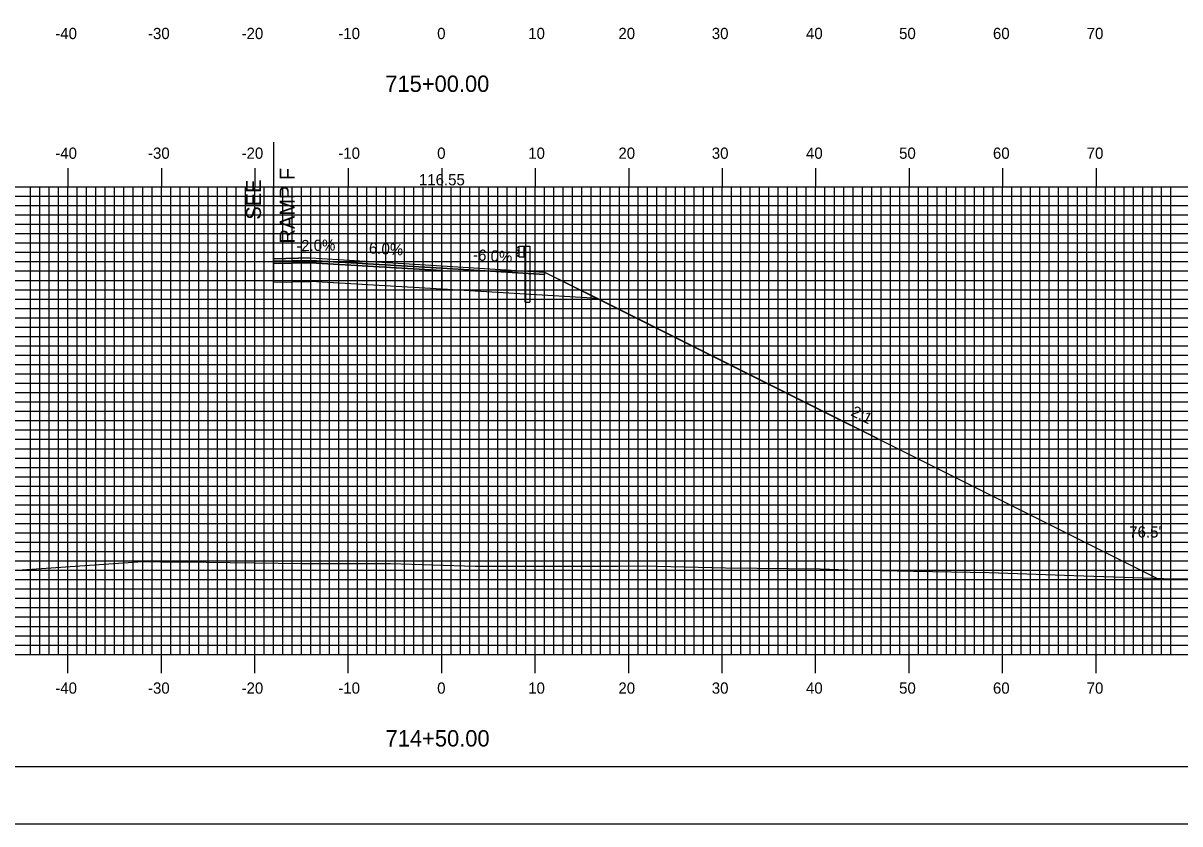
# Model space of a CAD drawing. Extents: x 856084 to 856427, y 364366 to 364586.
# Drawn here: x 856205 to 856328.8, y 364365.7 to 364451.3 of the extents above; entities that cross this region are included whole.
import ezdxf

# ---------------------------------------------------------------- set-up
doc = ezdxf.new("R2010")
doc.units = 0
for name, color, linetype in [('ANNOTATION', 7, 'Continuous'), ('BORDER', 7, 'Continuous'), ('D_Guardrail_Beam_Rt', 7, 'Continuous'), ('D_Roadway_Centerline', 7, 'Continuous'), ('D_Roadway_Centerline_Text', 7, 'Continuous'), ('D_Roadway_Edge_Shoulder', 7, 'Continuous'), ('D_Roadway_Edge_TW', 7, 'Continuous'), ('D_Roadway_Pavement', 7, 'Continuous'), ('D_Roadway_SlopeLines', 7, 'Continuous'), ('D_Roadway_SubGrade', 7, 'Continuous'), ('D_Text_Standard', 7, 'Continuous'), ('H_V ANNOTATION', 7, 'Continuous'), ('MAJOR', 7, 'Continuous'), ('MINOR', 7, 'Continuous'), ('PLOT BOUNDARY', 7, 'Continuous'), ('S_Roadway_Centerline', 7, 'Continuous')]:
    doc.layers.add(name, color=color, linetype=linetype)

msp = doc.modelspace()

# ---------------------------------------------------------------- linework, layer by layer
at = {"layer": 'BORDER'}
msp.add_lwpolyline([(856100.2, 364371.79), (856420.2, 364371.79), (856420.2, 364581.79), (856100.2, 364581.79)], close=True, dxfattribs=at)
at = {"layer": 'D_Guardrail_Beam_Rt'}
for p, q in [((856257.98, 364427.34), (856257.83, 364427.24)), ((856258.07, 364427.36), (856257.99, 364427.34)), ((856258.07, 364427.44), (856258.75, 364427.44)), ((856258.07, 364426.27), (856258.07, 364427.44)), ((856258.59, 364427.44), (856258.59, 364426.27)), ((856258.69, 364427.44), (856258.69, 364426.27)), ((856258.75, 364427.44), (856259.23, 364427.44)), ((856258.75, 364427.44), (856258.75, 364426.27)), ((856259.23, 364427.44), (856259.23, 364421.44)), ((856257.83, 364427.09), (856258.03, 364426.96)), ((856258.03, 364426.76), (856257.83, 364426.62)), ((856257.83, 364426.48), (856257.98, 364426.38)), ((856257.99, 364426.37), (856258.07, 364426.36)), ((856258.06, 364426.89), (856258.06, 364426.82)), ((856258.75, 364426.27), (856258.07, 364426.27)), ((856258.73, 364421.44), (856258.73, 364426.27)), ((856258.73, 364421.44), (856259.23, 364421.44))]:
    msp.add_line(p, q, dxfattribs=at)
for centre, major_axis, start_param, end_param in [((856258, 364427.3), (-0.0417, 0), 4.907132, 5.323254), ((856257.88, 364427.16), (-0.0877, 0), 5.323254, 7.243116), ((856257.88, 364426.55), (-0.0877, 0), 5.323254, 7.243116), ((856258, 364426.41), (-0.0417, 0), 0.959931, 1.376053), ((856257.98, 364426.89), (0.0789, 0), 0, 0.959931), ((856257.98, 364426.82), (0.0789, 0), 5.323254, 6.283185)]:
    msp.add_ellipse(centre, major_axis=major_axis, ratio=0.995501, start_param=start_param, end_param=end_param, dxfattribs=at)
at = {"layer": 'D_Roadway_Centerline'}
msp.add_lwpolyline([(856231.8, 364426.1), (856235.8, 364426.18), (856249.8, 364425.34), (856257.8, 364424.86), (856260.8, 364424.68), (856266.48, 364421.84), (856326.3, 364391.93)], dxfattribs=at)
at = {"layer": 'D_Roadway_Edge_Shoulder'}
for points in [[(856235.8, 364426.18), (856231.8, 364426.1), (856231.8, 364425.85), (856235.8, 364425.93)], [(856249.8, 364425.34), (856257.8, 364424.86), (856257.8, 364424.86), (856260.8, 364424.68), (856260.8, 364424.43), (856249.8, 364425.09)]]:
    msp.add_lwpolyline(points, close=True, dxfattribs=at)
at = {"layer": 'D_Roadway_Edge_TW'}
msp.add_lwpolyline([(856235.8, 364426.18), (856249.8, 364425.34), (856249.8, 364425.09), (856235.8, 364425.93)], close=True, dxfattribs=at)
at = {"layer": 'D_Roadway_Pavement'}
for points in [[(856235.8, 364425.93), (856231.8, 364425.85), (856231.8, 364425.6), (856235.8, 364425.68)], [(856235.8, 364425.93), (856249.8, 364425.09), (856249.8, 364424.84), (856235.8, 364425.68)]]:
    msp.add_lwpolyline(points, close=True, dxfattribs=at)
msp.add_lwpolyline([(856249.8, 364425.09), (856249.8, 364424.84)], dxfattribs=at)
msp.add_lwpolyline([(856249.8, 364425.09), (856249.8, 364424.84)], dxfattribs=at)
at = {"layer": 'D_Roadway_SlopeLines'}
msp.add_lwpolyline([(856260.8, 364424.68), (856326.3, 364391.93)], dxfattribs=at)
at = {"layer": 'D_Roadway_SubGrade'}
msp.add_line((856231.8, 364438.55), (856231.8, 364423.6), dxfattribs=at)
for points in [[(856235.8, 364425.68), (856231.8, 364425.6), (856231.8, 364425.85), (856231.8, 364426.1), (856231.8, 364423.6), (856235.8, 364423.68)], [(856235.8, 364425.68), (856249.8, 364424.84), (856249.8, 364422.84), (856235.8, 364423.68)], [(856249.8, 364424.84), (856249.8, 364425.09), (856260.8, 364424.43), (856260.8, 364424.68), (856266.48, 364421.84), (856249.8, 364422.84)]]:
    msp.add_lwpolyline(points, close=True, dxfattribs=at)
at = {"layer": 'MAJOR'}
for p, q in [((856209.8, 364435.79), (856209.8, 364433.79)), ((856219.8, 364435.79), (856219.8, 364433.79)), ((856229.8, 364435.79), (856229.8, 364433.79)), ((856239.8, 364435.79), (856239.8, 364433.79)), ((856249.8, 364435.79), (856249.8, 364433.79)), ((856259.8, 364435.79), (856259.8, 364433.79)), ((856269.8, 364435.79), (856269.8, 364433.79)), ((856279.8, 364435.79), (856279.8, 364433.79)), ((856289.8, 364435.79), (856289.8, 364433.79)), ((856299.8, 364435.79), (856299.8, 364433.79)), ((856309.8, 364435.79), (856309.8, 364433.79)), ((856319.8, 364435.79), (856319.8, 364433.79)), ((856109.8, 364433.79), (856389.8, 364433.79)), ((856109.8, 364433.79), (856389.8, 364433.79)), ((856209.8, 364383.79), (856209.8, 364433.79)), ((856219.8, 364383.79), (856219.8, 364433.79)), ((856229.8, 364383.79), (856229.8, 364433.79)), ((856239.8, 364383.79), (856239.8, 364433.79)), ((856249.8, 364383.79), (856249.8, 364433.79)), ((856259.8, 364383.79), (856259.8, 364433.79)), ((856269.8, 364383.79), (856269.8, 364433.79)), ((856279.8, 364383.79), (856279.8, 364433.79)), ((856289.8, 364383.79), (856289.8, 364433.79)), ((856299.8, 364383.79), (856299.8, 364433.79)), ((856309.8, 364383.79), (856309.8, 364433.79)), ((856319.8, 364383.79), (856319.8, 364433.79)), ((856109.8, 364428.79), (856389.8, 364428.79)), ((856109.8, 364423.79), (856389.8, 364423.79)), ((856109.8, 364418.79), (856389.8, 364418.79)), ((856109.8, 364413.79), (856389.8, 364413.79)), ((856109.8, 364408.79), (856389.8, 364408.79)), ((856109.8, 364403.79), (856389.8, 364403.79)), ((856109.8, 364398.79), (856389.8, 364398.79)), ((856109.8, 364393.79), (856389.8, 364393.79)), ((856109.8, 364388.79), (856389.8, 364388.79)), ((856109.8, 364383.79), (856389.8, 364383.79)), ((856109.8, 364383.79), (856389.8, 364383.79)), ((856209.8, 364381.78), (856209.8, 364383.79)), ((856219.8, 364381.78), (856219.8, 364383.79)), ((856229.8, 364381.78), (856229.8, 364383.79)), ((856239.8, 364381.78), (856239.8, 364383.79)), ((856249.8, 364381.78), (856249.8, 364383.79)), ((856259.8, 364381.78), (856259.8, 364383.79)), ((856269.8, 364381.78), (856269.8, 364383.79)), ((856279.8, 364381.78), (856279.8, 364383.79)), ((856289.8, 364381.78), (856289.8, 364383.79)), ((856299.8, 364381.78), (856299.8, 364383.79)), ((856309.8, 364381.78), (856309.8, 364383.79)), ((856319.8, 364381.78), (856319.8, 364383.79))]:
    msp.add_line(p, q, dxfattribs=at)
at = {"layer": 'MINOR'}
for p, q in [((856205.8, 364383.79), (856205.8, 364433.79)), ((856206.8, 364383.79), (856206.8, 364433.79)), ((856207.8, 364383.79), (856207.8, 364433.79)), ((856208.8, 364383.79), (856208.8, 364433.79)), ((856210.8, 364383.79), (856210.8, 364433.79)), ((856211.8, 364383.79), (856211.8, 364433.79)), ((856212.8, 364383.79), (856212.8, 364433.79)), ((856213.8, 364383.79), (856213.8, 364433.79)), ((856214.8, 364383.79), (856214.8, 364433.79)), ((856215.8, 364383.79), (856215.8, 364433.79)), ((856216.8, 364383.79), (856216.8, 364433.79)), ((856217.8, 364383.79), (856217.8, 364433.79)), ((856218.8, 364383.79), (856218.8, 364433.79)), ((856220.8, 364383.79), (856220.8, 364433.79)), ((856221.8, 364383.79), (856221.8, 364433.79)), ((856222.8, 364383.79), (856222.8, 364433.79)), ((856223.8, 364383.79), (856223.8, 364433.79)), ((856224.8, 364383.79), (856224.8, 364433.79)), ((856225.8, 364383.79), (856225.8, 364433.79)), ((856226.8, 364383.79), (856226.8, 364433.79)), ((856227.8, 364383.79), (856227.8, 364433.79)), ((856228.8, 364383.79), (856228.8, 364433.79)), ((856230.8, 364383.79), (856230.8, 364433.79)), ((856231.8, 364383.79), (856231.8, 364433.79)), ((856232.8, 364383.79), (856232.8, 364433.79)), ((856233.8, 364383.79), (856233.8, 364433.79)), ((856234.8, 364383.79), (856234.8, 364433.79)), ((856235.8, 364383.79), (856235.8, 364433.79)), ((856236.8, 364383.79), (856236.8, 364433.79)), ((856237.8, 364383.79), (856237.8, 364433.79)), ((856238.8, 364383.79), (856238.8, 364433.79)), ((856240.8, 364383.79), (856240.8, 364433.79)), ((856241.8, 364383.79), (856241.8, 364433.79)), ((856242.8, 364383.79), (856242.8, 364433.79)), ((856243.8, 364383.79), (856243.8, 364433.79)), ((856244.8, 364383.79), (856244.8, 364433.79)), ((856245.8, 364383.79), (856245.8, 364433.79)), ((856246.8, 364383.79), (856246.8, 364433.79)), ((856247.8, 364383.79), (856247.8, 364433.79)), ((856248.8, 364383.79), (856248.8, 364433.79)), ((856250.8, 364383.79), (856250.8, 364433.79)), ((856251.8, 364383.79), (856251.8, 364433.79)), ((856252.8, 364383.79), (856252.8, 364433.79)), ((856253.8, 364383.79), (856253.8, 364433.79)), ((856254.8, 364383.79), (856254.8, 364433.79)), ((856255.8, 364383.79), (856255.8, 364433.79)), ((856256.8, 364383.79), (856256.8, 364433.79)), ((856257.8, 364383.79), (856257.8, 364433.79)), ((856258.8, 364383.79), (856258.8, 364433.79)), ((856260.8, 364383.79), (856260.8, 364433.79)), ((856261.8, 364383.79), (856261.8, 364433.79)), ((856262.8, 364383.79), (856262.8, 364433.79)), ((856263.8, 364383.79), (856263.8, 364433.79)), ((856264.8, 364383.79), (856264.8, 364433.79)), ((856265.8, 364383.79), (856265.8, 364433.79)), ((856266.8, 364383.79), (856266.8, 364433.79)), ((856267.8, 364383.79), (856267.8, 364433.79)), ((856268.8, 364383.79), (856268.8, 364433.79)), ((856270.8, 364383.79), (856270.8, 364433.79)), ((856271.8, 364383.79), (856271.8, 364433.79)), ((856272.8, 364383.79), (856272.8, 364433.79)), ((856273.8, 364383.79), (856273.8, 364433.79)), ((856274.8, 364383.79), (856274.8, 364433.79)), ((856275.8, 364383.79), (856275.8, 364433.79)), ((856276.8, 364383.79), (856276.8, 364433.79)), ((856277.8, 364383.79), (856277.8, 364433.79)), ((856278.8, 364383.79), (856278.8, 364433.79)), ((856280.8, 364383.79), (856280.8, 364433.79)), ((856281.8, 364383.79), (856281.8, 364433.79)), ((856282.8, 364383.79), (856282.8, 364433.79)), ((856283.8, 364383.79), (856283.8, 364433.79)), ((856284.8, 364383.79), (856284.8, 364433.79)), ((856285.8, 364383.79), (856285.8, 364433.79)), ((856286.8, 364383.79), (856286.8, 364433.79)), ((856287.8, 364383.79), (856287.8, 364433.79)), ((856288.8, 364383.79), (856288.8, 364433.79)), ((856290.8, 364383.79), (856290.8, 364433.79)), ((856291.8, 364383.79), (856291.8, 364433.79)), ((856292.8, 364383.79), (856292.8, 364433.79)), ((856293.8, 364383.79), (856293.8, 364433.79)), ((856294.8, 364383.79), (856294.8, 364433.79)), ((856295.8, 364383.79), (856295.8, 364433.79)), ((856296.8, 364383.79), (856296.8, 364433.79)), ((856297.8, 364383.79), (856297.8, 364433.79)), ((856298.8, 364383.79), (856298.8, 364433.79)), ((856300.8, 364383.79), (856300.8, 364433.79)), ((856301.8, 364383.79), (856301.8, 364433.79)), ((856302.8, 364383.79), (856302.8, 364433.79)), ((856303.8, 364383.79), (856303.8, 364433.79)), ((856304.8, 364383.79), (856304.8, 364433.79)), ((856305.8, 364383.79), (856305.8, 364433.79)), ((856306.8, 364383.79), (856306.8, 364433.79)), ((856307.8, 364383.79), (856307.8, 364433.79)), ((856308.8, 364383.79), (856308.8, 364433.79)), ((856310.8, 364383.79), (856310.8, 364433.79)), ((856311.8, 364383.79), (856311.8, 364433.79)), ((856312.8, 364383.79), (856312.8, 364433.79)), ((856313.8, 364383.79), (856313.8, 364433.79)), ((856314.8, 364383.79), (856314.8, 364433.79)), ((856315.8, 364383.79), (856315.8, 364433.79)), ((856316.8, 364383.79), (856316.8, 364433.79)), ((856317.8, 364383.79), (856317.8, 364433.79)), ((856318.8, 364383.79), (856318.8, 364433.79)), ((856320.8, 364383.79), (856320.8, 364433.79)), ((856321.8, 364383.79), (856321.8, 364433.79)), ((856322.8, 364383.79), (856322.8, 364433.79)), ((856323.8, 364383.79), (856323.8, 364433.79)), ((856324.8, 364383.79), (856324.8, 364433.79)), ((856325.8, 364383.79), (856325.8, 364433.79)), ((856326.8, 364383.79), (856326.8, 364433.79)), ((856327.8, 364383.79), (856327.8, 364433.79)), ((856109.8, 364432.79), (856389.8, 364432.79)), ((856109.8, 364431.79), (856389.8, 364431.79)), ((856109.8, 364430.79), (856389.8, 364430.79)), ((856109.8, 364429.79), (856389.8, 364429.79)), ((856109.8, 364427.79), (856389.8, 364427.79)), ((856109.8, 364426.79), (856389.8, 364426.79)), ((856109.8, 364425.79), (856389.8, 364425.79)), ((856109.8, 364424.79), (856389.8, 364424.79)), ((856109.8, 364422.79), (856389.8, 364422.79)), ((856109.8, 364421.79), (856389.8, 364421.79)), ((856109.8, 364420.79), (856389.8, 364420.79)), ((856109.8, 364419.79), (856389.8, 364419.79)), ((856109.8, 364417.79), (856389.8, 364417.79)), ((856109.8, 364416.79), (856389.8, 364416.79)), ((856109.8, 364415.79), (856389.8, 364415.79)), ((856109.8, 364414.79), (856389.8, 364414.79)), ((856109.8, 364412.79), (856389.8, 364412.79)), ((856109.8, 364411.79), (856389.8, 364411.79)), ((856109.8, 364410.79), (856389.8, 364410.79)), ((856109.8, 364409.79), (856389.8, 364409.79)), ((856109.8, 364407.79), (856389.8, 364407.79)), ((856109.8, 364406.79), (856389.8, 364406.79)), ((856109.8, 364405.79), (856389.8, 364405.79)), ((856109.8, 364404.79), (856389.8, 364404.79)), ((856109.8, 364402.79), (856389.8, 364402.79)), ((856109.8, 364401.79), (856389.8, 364401.79)), ((856109.8, 364400.79), (856389.8, 364400.79)), ((856109.8, 364399.79), (856389.8, 364399.79)), ((856109.8, 364397.79), (856389.8, 364397.79)), ((856109.8, 364396.79), (856389.8, 364396.79)), ((856109.8, 364395.79), (856389.8, 364395.79)), ((856109.8, 364394.79), (856389.8, 364394.79)), ((856109.8, 364392.79), (856389.8, 364392.79)), ((856109.8, 364391.79), (856389.8, 364391.79)), ((856109.8, 364390.79), (856389.8, 364390.79)), ((856109.8, 364389.79), (856389.8, 364389.79)), ((856109.8, 364387.79), (856389.8, 364387.79)), ((856109.8, 364386.79), (856389.8, 364386.79)), ((856109.8, 364385.79), (856389.8, 364385.79)), ((856109.8, 364384.79), (856389.8, 364384.79))]:
    msp.add_line(p, q, dxfattribs=at)
at = {"layer": 'PLOT BOUNDARY'}
msp.add_lwpolyline([(856084.01, 364365.67), (856424.01, 364365.67), (856424.01, 364585.67), (856084.01, 364585.67)], close=True, dxfattribs=at)
at = {"layer": 'S_Roadway_Centerline'}
msp.add_lwpolyline([(856204.92, 364392.84), (856217.77, 364393.71), (856219.72, 364393.7), (856224.61, 364393.64), (856234.85, 364393.52), (856244.33, 364393.51), (856253.38, 364393.22), (856268.59, 364393.23), (856271.4, 364393.25), (856280.16, 364393.06), (856290.28, 364392.94), (856293.26, 364392.83), (856300.26, 364392.7), (856308.35, 364392.54), (856317.41, 364392.24), (856327.03, 364391.9), (856329.64, 364391.87)], dxfattribs=at)

# ---------------------------------------------------------------- texts
at = {"layer": 'ANNOTATION'}
for s, height, rotation, p in [('RAMP F', 1.6, 90, (856234.06, 364427.73)), ('SEE', 1.6, 90, (856230.46, 364430.28)), ('-2.0%', 1.2, 1.1458, (856234.24, 364426.89)), ('6.0%', 1.2, 356.5664, (856241.98, 364426.67)), ('-6.0%', 1.2, 356.5664, (856253.13, 364425.94)), ('2:1', 1.2, 333.4349, (856293.48, 364409.37))]:
    msp.add_text(s, height=height, rotation=rotation, dxfattribs=at).set_placement(p)
at = {"layer": 'D_Roadway_Centerline_Text'}
msp.add_text('116.55', height=1.2, dxfattribs=at).set_placement((856247.36, 364433.95))
at = {"layer": 'D_Text_Standard'}
msp.add_text("76.5'", height=1.2, dxfattribs=at).set_placement((856323.35, 364396.29))
at = {"layer": 'H_V ANNOTATION'}
for s, height, p in [('-40', 1.2, (856208.45, 364449.59)), ('-30', 1.2, (856218.37, 364449.59)), ('-20', 1.2, (856228.38, 364449.59)), ('-10', 1.2, (856238.73, 364449.59)), ('0', 1.2, (856249.31, 364449.59)), ('10', 1.2, (856259.05, 364449.59)), ('20', 1.2, (856268.7, 364449.59)), ('30', 1.2, (856278.69, 364449.59)), ('40', 1.2, (856288.77, 364449.59)), ('50', 1.2, (856298.73, 364449.59)), ('60', 1.2, (856308.77, 364449.59)), ('70', 1.2, (856318.8, 364449.59)), ('715+00.00', 1.75, (856243.76, 364443.94)), ('-40', 1.2, (856208.45, 364436.79)), ('-30', 1.2, (856218.37, 364436.79)), ('-20', 1.2, (856228.38, 364436.79)), ('-10', 1.2, (856238.73, 364436.79)), ('0', 1.2, (856249.31, 364436.79)), ('10', 1.2, (856259.05, 364436.79)), ('20', 1.2, (856268.7, 364436.79)), ('30', 1.2, (856278.69, 364436.79)), ('40', 1.2, (856288.77, 364436.79)), ('50', 1.2, (856298.73, 364436.79)), ('60', 1.2, (856308.77, 364436.79)), ('70', 1.2, (856318.8, 364436.79)), ('-40', 1.2, (856208.45, 364379.59)), ('-30', 1.2, (856218.37, 364379.59)), ('-20', 1.2, (856228.38, 364379.59)), ('-10', 1.2, (856238.73, 364379.59)), ('0', 1.2, (856249.31, 364379.59)), ('10', 1.2, (856259.05, 364379.59)), ('20', 1.2, (856268.7, 364379.59)), ('30', 1.2, (856278.69, 364379.59)), ('40', 1.2, (856288.77, 364379.59)), ('50', 1.2, (856298.73, 364379.59)), ('60', 1.2, (856308.77, 364379.59)), ('70', 1.2, (856318.8, 364379.59)), ('714+50.00', 1.75, (856243.79, 364373.94))]:
    msp.add_text(s, height=height, dxfattribs=at).set_placement(p)

doc.saveas('drawing.dxf')
